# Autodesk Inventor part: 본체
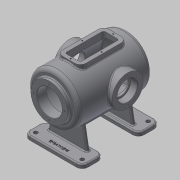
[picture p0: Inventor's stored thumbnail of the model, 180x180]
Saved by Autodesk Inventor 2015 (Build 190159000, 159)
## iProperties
Created: 2016-02
Part Number: 본체
Material: 일반
Document SubType Name: Modeling
Designer: mduedu
Density: 1 g/cm^3
Appearance: 기본값
Author: mduedu
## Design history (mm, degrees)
sketch "스케치2"
  geometry: L1 (0, 100)-(0, -100); L2 (65, -87.083)-(65, 100); L3 (65, 100)-(0, 100); A1 r 170 centre (0, 70) between (0, -100) and (65, -87.083); 2 further points
  constraints: 6 end point, 2 point on circle, 1 centre point, 1 coincident, 1 horizontal, 1 midpoint, 1 parallel, 1 point on line, 1 vertical
  dimensions: "d3" = 200 distance of L1.start L1.end; "d5" = 130 diameter of L2 L1; "d6" = 170 radius of A1
revolve "회전1" sketch "스케치2" stored, may be unused: angle "d7" = 90 deg
sketch "스케치3"
  geometry: C1 r 47.5 at (0, 0); 1 further point
  constraints: 1 centre point, 1 coincident
  dimensions: "d8" = 95 diameter of C1
extrude "돌출2" join sketch "스케치3" distance "d10" = 10; taper "d11" = 0 deg
sketch "스케치5"
  geometry: L1 (47.5, 110)-(47.5, 100) reference; L2 (47.5, 100)-(65, 100) reference; L3 (65, 100)-(65, -87.083) reference; L4 (-65, -87.083)-(-65, 100) reference; L5 (-65, 100)-(-47.5, 100) reference; L6 (-47.5, 100)-(-47.5, 110) reference; L7 (-47.5, 110)-(47.5, 110) reference; L8 (55, 85)-(55, -80.25); L9 (0, 85)-(55, 85); L10 (0, 85)-(0, -90); A1 r 170 centre (0, 70) between (-65, -87.083) and (0, -100) reference; A2 r 170 centre (0, 70) between (0, -100) and (65, -87.083) reference; A3 r 160 centre (0, 70) between (0, -90) and (55, -80.25); 1 further point
  constraints: 6 end point, 2 point on circle, 1 centre point, 1 parallel, 1 perpendicular, 1 point on line, 1 vertical
  dimensions: "d13" = 10 distance between parallel lines of L3 L8; "d14" = 10 radial gap between concentric circles of A3 A1; "d15" = 15 distance between parallel lines of L9 L2
revolve "회전2" sketch "스케치5" stored, may be unused: angle "d16" = 90 deg
hole "구멍1" diameter "d19" = 65; stored, may be unused: countersink angle "d23" = 90 deg, drill point angle "d25" = 118 deg; dims "d17" = 10, "d18" = 10, "d20" = 6, "d21" = 4, "d22" = 2, "d24" = 8
node "작업 평면1"
sketch "스케치6"
  geometry: L1 (47.5, 110)-(-47.5, 110) reference; C1 r 40 at (0, -17); 1 further point
  constraints: 1 centre point, 1 vertical alignment
  dimensions: "d27" = 80 diameter of C1; "d29" = 127 distance from line of C1.centre L1
extrude "돌출3" join sketch "스케치6" stored distance "d30" = 10; taper "d31" = 0 deg
hole "구멍2" diameter "d34" = 42; stored, may be unused: countersink angle "d38" = 90 deg, drill point angle "d40" = 118 deg; dims "d32" = 10, "d33" = 10, "d35" = 6, "d36" = 52, "d37" = 18, "d39" = 8
sketch "스케치7" dims "d41" = 65
  geometry: C1 r 40 at (0, 0) reference; 3 further points
  constraints: 2 vertical alignment, 1 coincident, 2 other
hole "구멍3" sketch "스케치7" at (0, 32.5) diameter "d43" = 3.242; stored, may be unused: countersink angle "d47" = 90 deg, drill point angle "d49" = 118 deg; dims "d44" = 11, "d45" = 13, "d46" = 18, "d48" = 13
sketch "스케치8" dims "d53" = 80
  geometry: 3 further points
  constraints: 2 vertical alignment, 1 coincident, 2 other
hole "구멍4" sketch "스케치8" at (0, 40) diameter "d56" = 3.242; stored, may be unused: countersink angle "d60" = 90 deg, drill point angle "d62" = 118 deg; dims "d57" = 11, "d58" = 13, "d59" = 18, "d61" = 13
fillet "모깎기1" dims "d66" = 10
fillet "모깎기2" dims "d67" = 3
fillet "모깎기3" dims "d68" = 0.3
chamfer "모따기1" distance "d69" = 1; stored, may be unused: second distance "d70" = 2, angle "d71" = 45 deg
node "작업 평면2"
sketch "스케치9"
  geometry: L1 (75, 100)-(-75, 100); L2 (-75, 100)-(-75, -100); L3 (-75, -100)-(75, -100); L4 (75, -100)-(75, 100); 1 further point
  constraints: 8 end point, 2 parallel, 1 horizontal, 1 perpendicular
  dimensions: "d73" = 200 distance of L3.end L1.start; "d75" = 150 distance of L2.end L3.end; "d76" = 100 distance from line of L1 point (0, 0); "d77" = 75 distance from line of L4 point (0, 0)
extrude "돌출4" join sketch "스케치9" distance "d78" = 10; taper "d79" = 0 deg
sketch "스케치10"
  geometry: L1 (-75, -100)-(75, -100) reference; L2 (75, 100)-(-75, 100) reference; L3 (0, -100)-(0, 100); L4 (-75, 100)-(-75, -100) reference; L5 (75, -100)-(75, 100) reference; L6 (-75, 0)-(75, 0); L7 (-50, -63)-(50, -63); L8 (50, -63)-(50, -55); L9 (50, -55)-(-50, -55); L10 (-50, -55)-(-50, -63); L11 (-50, 63)-(50, 63); L12 (50, 63)-(50, 55); L13 (50, 55)-(-50, 55); L14 (-50, 55)-(-50, 63); 1 further point
  constraints: 20 end point, 4 midpoint, 4 symmetric about line, 2 parallel, 1 horizontal, 1 perpendicular, 1 other
  dimensions: "d80" = 8 distance of L9.end L7.start; "d82" = 100 distance of L7.start L7.end; "d83" = 55 distance between parallel lines of L9 L6
extrude "돌출5" join sketch "스케치10" stored distance "d84" = 10; taper "d85" = 0 deg
feature "면 기울기1" dims angle "d86" = 10 deg
sketch "스케치11"
  geometry: L1 (-110, 55)-(-51.482, 55) reference; L2 (-110, -55)-(-51.482, -55) reference; L3 (-95, 55)-(-95, -55); L4 (-65, 90)-(-65, -80.25) reference; 1 further point
  constraints: 2 end point, 2 point on line, 1 perpendicular
  dimensions: "d87" = 30 distance between parallel lines of L3 L4
feature "리브1" sketch "스케치11" dims "d88" = 1, "d89" = 8, "d90" = 0, "d91" = 0, "d92" = 1, "d93" = 1
sketch "스케치12"
  geometry: L1 (-110, 55)-(-51.482, 55) reference; L2 (-110, -55)-(-51.482, -55) reference; L3 (-110, 100)-(-110, -100) reference; L4 (-120, 152)-(-120, -142) reference; L5 (-110, 45)-(-120, 45); L6 (-120, 45)-(-120, -45); L7 (-120, -45)-(-110, -45); L8 (-110, -45)-(-110, 45); 1 further point
  constraints: 8 end point, 2 parallel, 2 point on line, 1 horizontal, 1 perpendicular
  dimensions: "d94" = 10 distance between parallel lines of L7 L2; "d95" = 10 distance between parallel lines of L1 L5
extrude "돌출6" cut sketch "스케치12" stored distance "d96" = 10; taper "d97" = 0 deg
fillet "모깎기4" dims "d98" = 15
sketch "스케치13"
  geometry: C1 r 5 at (-60, -85); C2 r 5 at (60, -85); C3 r 5 at (60, 85); C4 r 5 at (-60, 85); A1 r 15 centre (-60, -85) between (-75, -85) and (-60, -100) reference; A2 r 15 centre (60, -85) between (60, -100) and (75, -85) reference; A3 r 15 centre (60, 85) between (75, 85) and (60, 100) reference; A4 r 15 centre (-60, 85) between (-60, 100) and (-75, 85) reference; 1 further point
  constraints: 4 centre point, 4 coincident, 3 equal radius
  dimensions: "d99" = 10 diameter of C1
extrude "돌출7" cut sketch "스케치13" stored distance "d101" = 10; taper "d102" = 0 deg
fillet "모깎기5" dims "d103" = 3, "d104" = 3
fillet "모깎기6" dims "d105" = 3
sketch "스케치14"
  geometry: L1 (-60, -100)-(60, -100) reference; 2 further points
  constraints: 1 vertical alignment, 1 other
  dimensions: "d106" = 15 distance from line of point (0, -85) L1
feature "엠보싱1" sketch "스케치14" dims "d3" = 200, "d5" = 130, "d6" = 170, "d14" = 10, "d107" = 0.5, "d108" = 0
node "작업 평면3"
sketch "스케치15"
  geometry: L1 (-30, 60)-(30, 60); L2 (30, 60)-(30, -60); L3 (30, -60)-(-30, -60); L4 (-30, -60)-(-30, 60); 2 further points
  constraints: 8 end point, 2 parallel, 1 horizontal, 1 midpoint, 1 perpendicular, 1 vertical alignment
  dimensions: "d110" = 60 distance of L2.end L3.end; "d112" = 60 distance from line of L3 point (0, 0); "d113" = 120 distance of L1.end L2.end
extrude "돌출8" join sketch "스케치15" stored distance "d114" = 10; taper "d115" = 0 deg
fillet "모깎기7" dims "d116" = 15
sketch "스케치16"
  geometry: L1 (-30, -45)-(-30, 45) reference; L2 (-15, 60)-(15, 60) reference; L3 (30, 45)-(30, -45) reference; L4 (15, -60)-(-15, -60) reference; L5 (15, 50)-(-15, 50); L6 (-20, 45)-(-20, -45); L7 (-15, -50)-(15, -50); L8 (20, -45)-(20, 45); A1 r 15 centre (-15, -45) between (-30, -45) and (-15, -60) reference; A2 r 15 centre (-15, 45) between (-15, 60) and (-30, 45) reference; A3 r 15 centre (15, 45) between (30, 45) and (15, 60) reference; A4 r 15 centre (15, -45) between (15, -60) and (30, -45) reference; A5 r 5 centre (-15, 45) between (-15, 50) and (-20, 45); A6 r 5 centre (-15, -45) between (-20, -45) and (-15, -50); A7 r 5 centre (15, -45) between (15, -50) and (20, -45); A8 r 5 centre (15, 45) between (20, 45) and (15, 50); 1 further point
  constraints: 8 end point, 8 point on circle, 4 centre point, 7 other
  dimensions: "d117" = 10 distance between parallel lines of L6 L1
extrude "돌출9" cut sketch "스케치16" stored distance "d118" = 10; taper "d119" = 0 deg
fillet "모깎기8" dims "d120" = 3
sketch "스케치17"
  geometry: L1 (-30, -45)-(-30, 45) reference; L2 (-15, 60)-(15, 60) reference; L3 (30, 45)-(30, -45) reference; L4 (15, -60)-(-15, -60) reference; L5 (20, -45)-(20, 45) reference; L6 (15, 50)-(-15, 50) reference; L7 (-20, 45)-(-20, -45) reference; L8 (-15, -50)-(15, -50) reference; L9 (15, 55)-(-15, 55); L10 (-25, 45)-(-25, -45); L11 (-15, -55)-(15, -55); L12 (25, -45)-(25, 45); A1 r 15 centre (-15, 45) between (-15, 60) and (-30, 45) reference; A2 r 15 centre (15, 45) between (30, 45) and (15, 60) reference; A3 r 15 centre (15, -45) between (15, -60) and (30, -45) reference; A4 r 15 centre (-15, -45) between (-30, -45) and (-15, -60) reference; A5 r 5 centre (15, -45) between (15, -50) and (20, -45) reference; A6 r 5 centre (15, 45) between (20, 45) and (15, 50) reference; A7 r 5 centre (-15, 45) between (-15, 50) and (-20, 45) reference; A8 r 5 centre (-15, -45) between (-20, -45) and (-15, -50) reference; A9 r 10 centre (-15, 45) between (-15, 55) and (-25, 45); A10 r 10 centre (-15, -45) between (-25, -45) and (-15, -55); A11 r 10 centre (15, -45) between (15, -55) and (25, -45); A12 r 10 centre (15, 45) between (25, 45) and (15, 55); 5 further points
  constraints: 8 end point, 8 point on circle, 4 centre point, 4 midpoint, 7 other
  dimensions: "d121" = 5 distance between parallel lines of L10 L1
hole "구멍5" sketch "스케치17" at (0, 55), (25, 0), (0, -55), (-25, 0) diameter "d122" = 3.242; stored, may be unused: countersink angle "d126" = 90 deg, drill point angle "d128" = 118 deg; dims "d123" = 9, "d124" = 13, "d125" = 18, "d127" = 11
fillet "모깎기9" dims "d129" = 3
node "솔리드2"
pattern_circular "원형 패턴1" dims angle "d51" = 360 deg
mirror "대칭1"
pattern_circular "원형 패턴2" dims angle "d64" = 360 deg
node "절단 모서리 투영1"
node "절단 모서리 투영2"
node "절단 모서리 투영3"
other parameters: "d26" = 75
